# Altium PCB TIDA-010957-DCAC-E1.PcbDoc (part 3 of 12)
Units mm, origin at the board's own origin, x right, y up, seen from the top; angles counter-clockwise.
Board outline 300 x 300 mm, 4 copper layers (Top Layer, Layer 1, Layer 2, Bottom Layer), stack 1.787 mm thick; 1159 components, 619 nets, 3431 pads, 2942 vias.
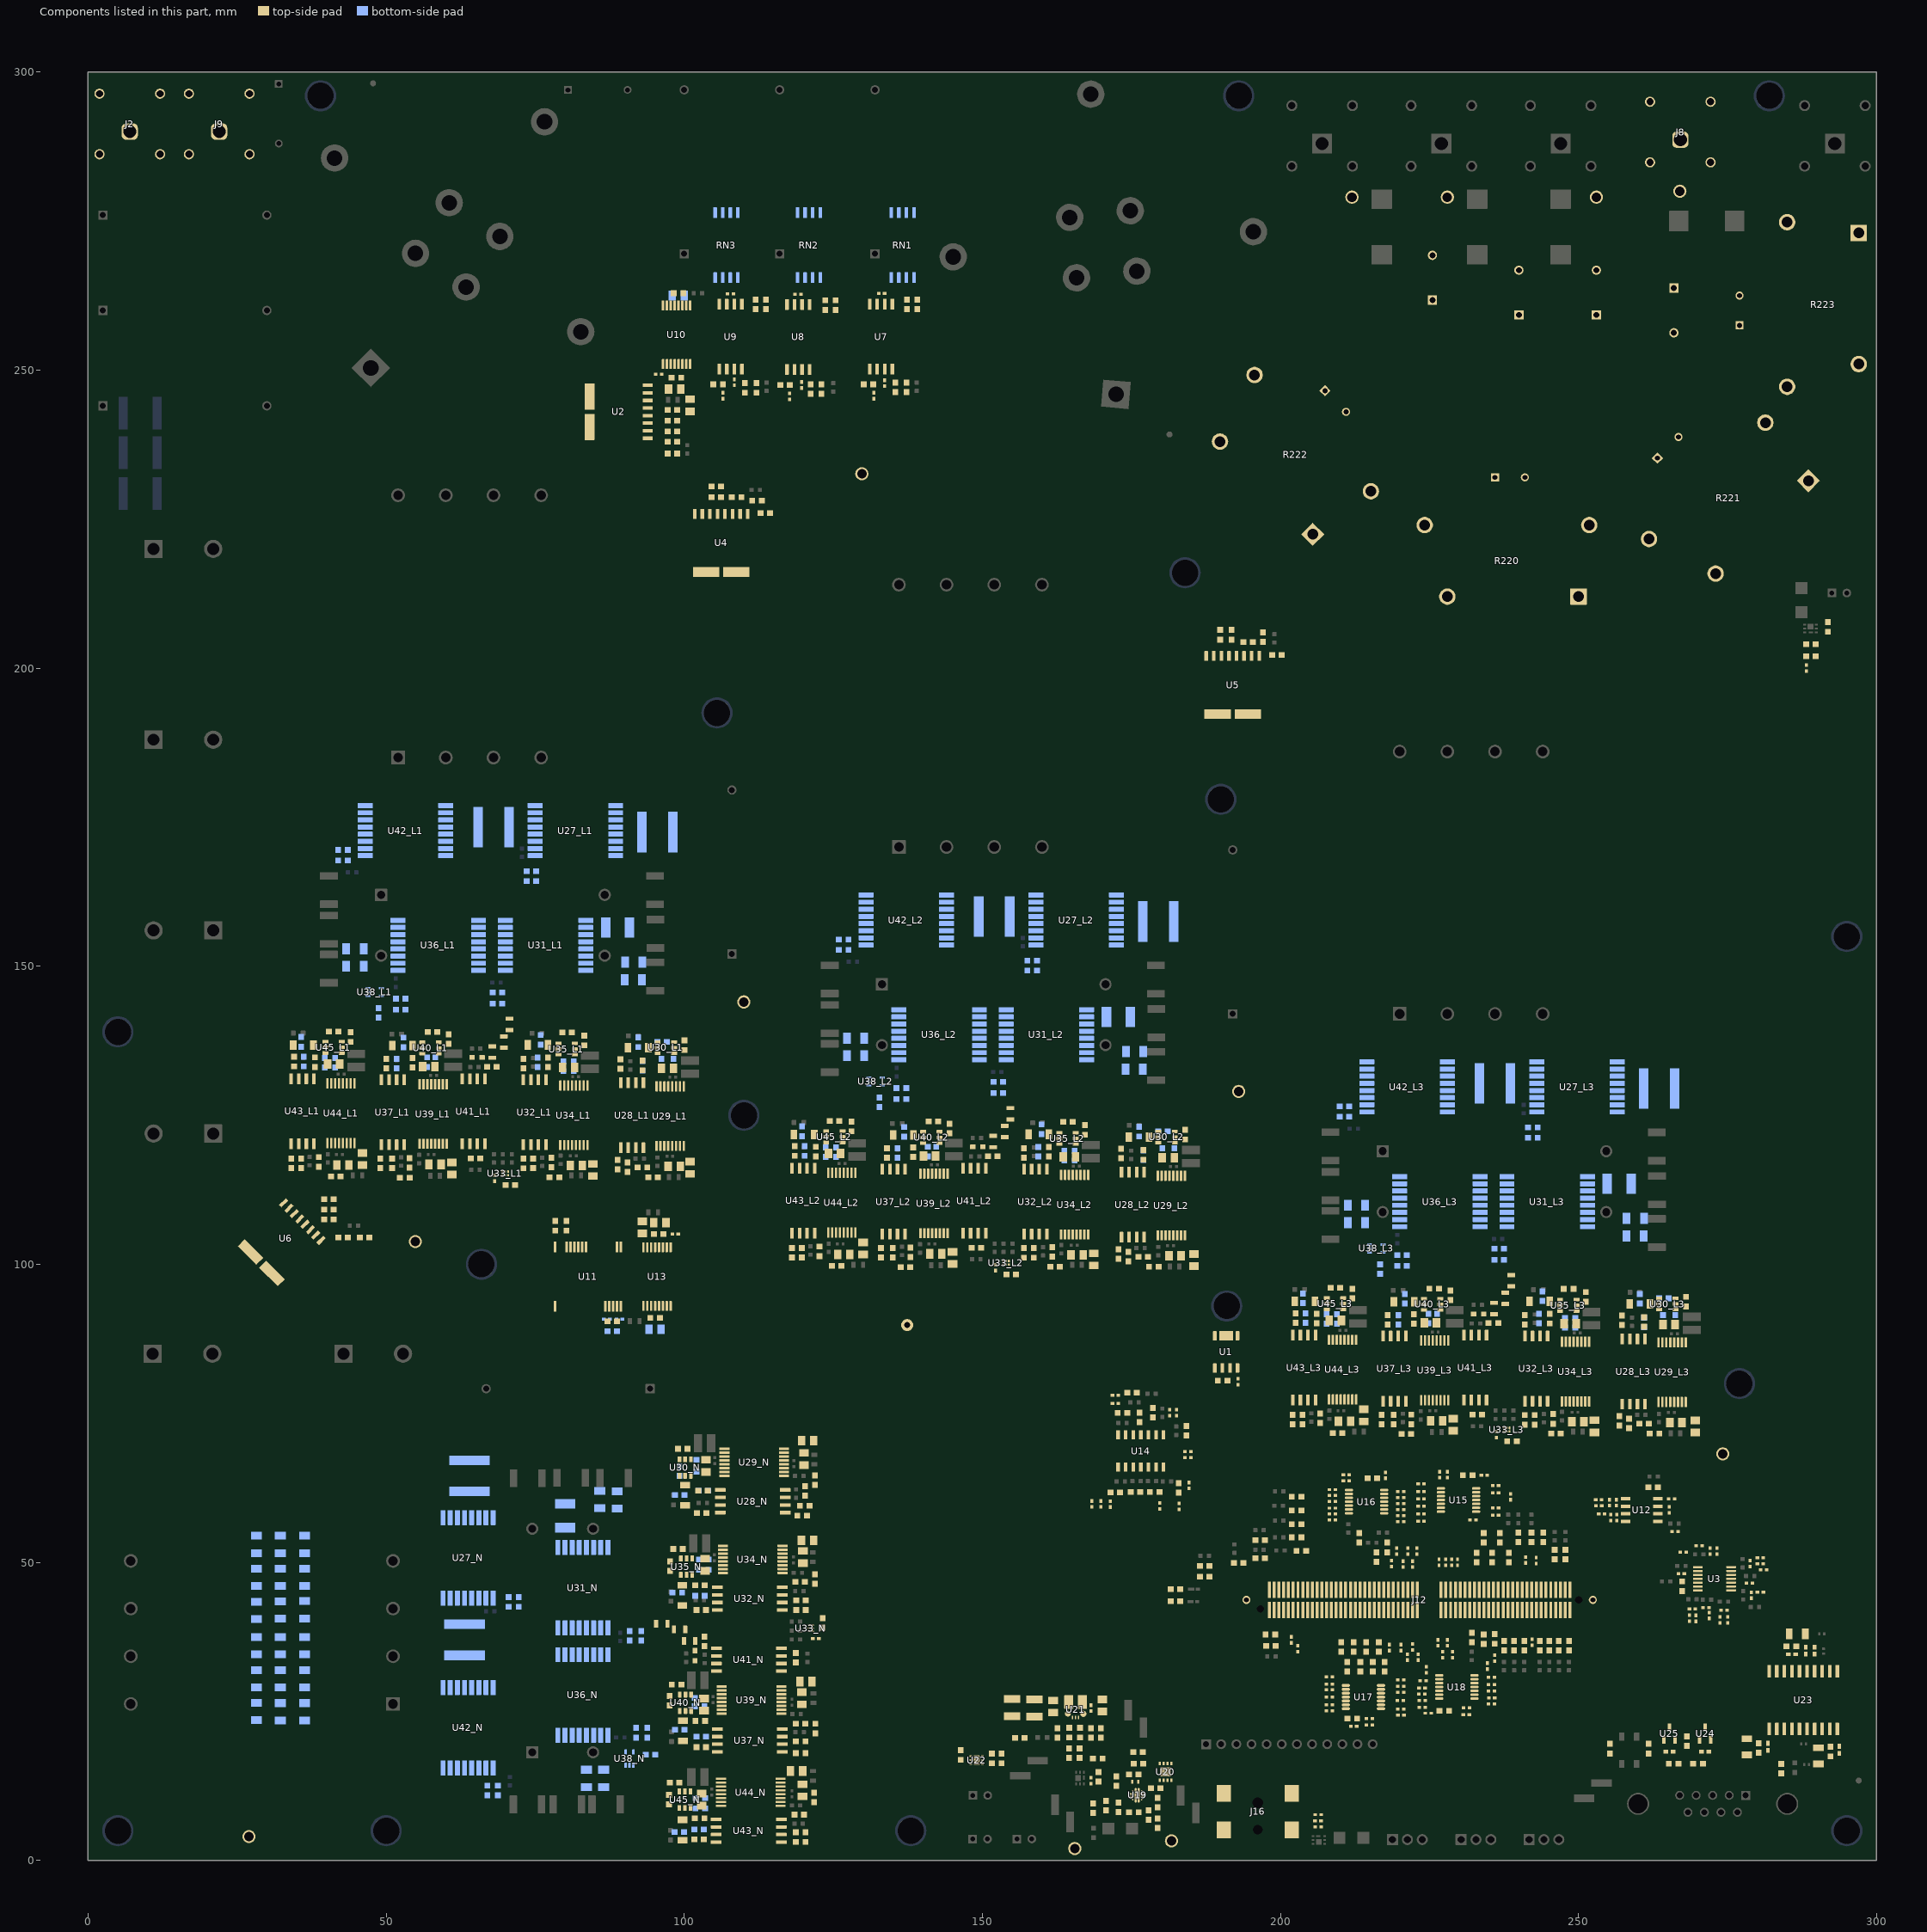
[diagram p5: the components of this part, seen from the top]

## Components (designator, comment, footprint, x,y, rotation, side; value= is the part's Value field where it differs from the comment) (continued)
R44 "ERJ-2RKF33R0X" 0402L 228.9,34.5 r90 top value=33.0
R45 "ERJ-2RKF33R0X" 0402L 228.7,50 r270 top value=33.0
R46 "ERJ-2RKF33R0X" 0402L 228,36.5 r90 top value=33.0
R47 "ERJ-2RKF33R0X" 0402L 227.7,50 r270 top value=33.0
R48 "ERJ-2RKF33R0X" 0402L 227.2,34.5 r90 top value=33.0
R49 "ERJ-2RKF33R0X" 0402L 226.6,50 r270 top value=33.0
R50 "ERJ-2RKF33R0X" 0402L 226.4,36.5 r90 top value=33.0
R51 "ERJ-2RKF33R0X" 0402L 222.9,51.9 r270 top value=33.0
R52 "ERJ-2RKF33R0X" 0402L 223.1,34.1 r90 top value=33.0
R53 "ERJ-2RKF33R0X" 0402L 222.2,49.7 r270 top value=33.0
R54 "ERJ-2RKF33R0X" 0402L 222.2,35.8 r90 top value=33.0
R55 "ERJ-2RKF33R0X" 0402L 221.4,51.9 r270 top value=33.0
R56 "ERJ-2RKF33R0X" 0402L 221.3,34.1 r90 top value=33.0
R57 "ERJ-2RKF33R0X" 0402L 220.6,49.7 r270 top value=33.0
R58 "ERJ-2RKF33R0X" 0402L 220.2,35.7 r90 top value=33.0
R59 "ERJ-2RKF33R0X" 0402L 219.5,51.9 r270 top value=33.0
R60 "ERJ-2RKF33R0X" 0402L 218.6,49.8 r270 top value=33.0
R61 "ERJ-2RKF33R0X" 0402L 218.3,35.7 r90 top value=33.0
R62 "RCS06030000Z0EA" 0603 217.9,52.5 r90 top value=0
R63 "RCS06030000Z0EA" 0603 217.5,32.5 r90 top value=0
R64 "RCS06030000Z0EA" 0603 216.1,50.9 r90 top value=0
R65 "RCS06030000Z0EA" 0603 216.5,35.8 r90 top value=0
R66 "RCS06030000Z0EA" 0603 213.2,54.1 r90 top value=0
R67 "RCS06030000Z0EA" 0603 215.5,32.5 r90 top value=0
R68 "RCS06030000Z0EA" 0603 202.7,61 r180 top value=0
R69 "RCS06030000Z0EA" 0603 214.4,35.8 r90 top value=0
R70 "RCS06030000Z0EA" 0603 202.7,58.7 r180 top value=0
R71 "RCS06030000Z0EA" 0603 213.4,32.5 r90 top value=0
R72 "RCS06030000Z0EA" 0603 202.7,56.4 r180 top value=0
R73 "RCS06030000Z0EA" 0603 202.7,54.2 r180 top value=0
R74 "RCS06030000Z0EA" 0603 196.589,53.741 r180 top value=0
R75 "RCS06030000Z0EA" 0603 203.5,51.9 r180 top value=0
R76 "RCS06030000Z0EA" 0603 196.6,50.7 r180 top value=0
R77 "RCS06030000Z0EA" 0603 193,49.9 r180 top value=0
R78 "RCS06030000Z0EA" 0603 187.3,49.4 r180 top value=0
R79 "ERJ-2RKF33R0X" 0402L 202.9,35.5 r90 top value=33.0
R80 "ERJ-2RKF33R0X" 0402L 201.8,37 r90 top value=33.0
R81 "RC0603JR-07680RL" 0603 182.4,45.5 r0 top value=680
R82 "RC0603JR-07680RL" 0603 182.4,43.5 r0 top value=680
R83 "PTCEL13R600LBE" FP-PTCEL13R600LBE_RADIAL-MFG 238.5,232 r0 top value=60Ω
R84 "RCS06030000Z0EA" 0603 212.3,35.8 r90 top value=0
R85 "PTCEL13R600LBE" FP-PTCEL13R600LBE_RADIAL-MFG 265,237 r45 top value=60Ω
R86 "RCS06030000Z0EA" 0603 211.2,32.5 r90 top value=0
R87 "PTCEL13R600LBE" FP-PTCEL13R600LBE_RADIAL-MFG 209.232,244.768 r315 top value=60Ω
R88 "RCS06030000Z0EA" 0603 210.2,35.8 r90 top value=0
R89 "IsoM5-275-B-L2" FP-IsoM5-275-B-L2_RADIAL-MFG 253,263 r90 top
R90 "IsoM5-275-B-L2" FP-IsoM5-275-B-L2_RADIAL-MFG 240,263 r90 top
R91 "IsoM5-275-B-L2" FP-IsoM5-275-B-L2_RADIAL-MFG 225.5,265.5 r90 top
R92 "PTCEL13R600LBE" FP-PTCEL13R600LBE_RADIAL-MFG 277,260 r90 top value=60Ω
R93 "CRCW0603499RFKEAC" 0603 284,15.4 r90 top value=499
R94 "IsoM5-275-B-L2" FP-IsoM5-275-B-L2_RADIAL-MFG 266,260 r270 top
R96 "ERJ-2RKF1000X" 0402L 288.2,200 r90 top value=100
R97 "CRCW060310K0FKEA" 0603 289,202 r180 top value=10.0k
R98 "MCS0402MD1002BE100" 0402L 271.4,42.4 r180 top value=10.0k
R99 "CRCW060310K0FKEA" 0603 98,236 r0 top value=10.0k
R100 "MCS0402MD1002BE100" 0402L 271.9,41.1 r270 top value=10.0k
R101 "CRCW0402309RFKED" 0402L 269.7,40.6 r270 top value=309
R102 "MCS0402MD1002BE100" 0402L 268.6,40.645 r270 top value=10.0k
R103 "MCS0402MD1002BE100" 0402L 269.1,42.2 r180 top value=10.0k
R104 "RC0603FR-0743K2L" 0603 98,239.7 r180 top value=43.2k
R105 "CRCW060310K0FKEA" 0603 98,241.5 r0 top value=10.0k
R106 "MCS0402MD1002BE100" 0402L 278.996,44.485 r270 top value=10.0k
R107 "MCS0402MD1002BE100" 0402L 280.5,45 r0 top value=10.0k
R108 "CRCW0402309RFKED" 0402L 275.05,40.363 r270 top value=309
R109 "CRCW060310K0FKEA" 0603 113.6,226 r0 top value=10.0k
R110 "MCS0402MD1002BE100" 0402L 273.75,40.363 r270 top value=10.0k
R111 "MCS0402MD1002BE100" 0402L 274.4,42 r180 top value=10.0k
R112 "RC0603FR-0743K2L" 0603 108.8,228.7 r0 top value=43.2k
R113 "CRCW060310K0FKEA" 0603 105.4,228.7 r0 top value=10.0k
R114 "MCS0402MD1002BE100" 0402L 278.685,46.5 r0 top value=10.0k
R115 "MCS0402MD1002BE100" 0402L 281.067,48.732 r0 top value=10.0k
R116 "CRCW0402309RFKED" 0402L 280.493,50.8 r0 top value=309
R117 "CRCW060310K0FKEA" 0603 199.4,202.2 r0 top value=10.0k
R118 "MCS0402MD1002BE100" 0402L 280.493,49.75 r0 top value=10.0k
R119 "MCS0402MD1002BE100" 0402L 278.8,49.8 r270 top value=10.0k
R120 "RC0603FR-0743K2L" 0603 194.6,204.4 r0 top value=43.2k
R121 "CRCW060310K0FKEA" 0603 189.9,205.6 r270 top value=10.0k
R122 "MCS0402MD1002BE100" 0402L 267.25,48.119 r180 top value=10.0k
R123 "CRCW060310K0FKEA" 0603 42.8,104.5 r0 top value=10.0k
R124 "MCS0402MD1002BE100" 0402L 273.2,51.9 r90 top value=10.0k
R125 "CRCW0402309RFKED" 0402L 267.55,51.684 r180 top value=309
R126 "MCS0402MD1002BE100" 0402L 272.1,51.9 r90 top value=10.0k
R127 "MCS0402MD1002BE100" 0402L 270.25,52.807 r0 top value=10.0k
R128 "RC0603FR-0743K2L" 0603 40.425,107.5 r0 top value=43.2k
R129 "CRCW060310K0FKEA" 0603 40.425,109.2 r180 top value=10.0k
R130 "ERJ-2RKF1000X" 0402L 133.6,247.8 r270 top value=100
R131 "ERJ-2RKF1000X" 0402L 131.8,245.7 r270 top value=100
R132 "ERJ-2RKF1000X" 0402L 119.705,247.494 r270 top value=100
R133 "ERJ-2RKF1000X" 0402L 117.7,245.6 r270 top value=100
R134 "ERJ-2RKF1000X" 0402L 108.405,247.945 r270 top value=100
R135 "ERJ-2RKF1000X" 0402L 106.5,245.7 r270 top value=100
R136 "CRCW040230K0FKED" 0402L 95.7,249.3 r0 top value=30.0k
R137 "ERA-2AEB153X" 0402L 256.4,57.5 r270 top value=15.0k
R138 "RC0402JR-070RL" 0402L 87.029,90.768 r180 bottom value=0
R139 "MCS0402MD1002BE100" 0402L 253.883,58.14 r180 top value=10.0k
R140 "CRCW0402309RFKED" 0402L 253.383,60.513 r180 top value=309
R141 "MCS0402MD1002BE100" 0402L 253.4,59.5 r180 top value=10.0k
R142 "ERA-2AEB153X" 0402L 256.35,60.013 r90 top value=15.0k
R143 "CRCW040230K0FKED" 0402L 98.5,105.1 r0 top value=30.0k
R144 "RT0603BRD0715K6L" 0603 178.6,75.1 r90 top value=15.6k
R145 "MCS0402MD1002BE100" 0402L 181.428,75.104 r90 top value=10.0k
R146 "ERJ-2RKF33R0X" 0402L 169.9,59.8 r270 top value=33.0
R147 "MCS0402MD1002BE100" 0402L 182.59,75.109 r90 top value=10.0k
R148 "RT0603BRD0715K6L" 0603 184.209,72.084 r90 top value=15.6k
R149 "RT0603BRD0715K6L" 0603 175.091,78.475 r0 top value=15.6k
R150 "MCS0402MD1002BE100" 0402L 172.32,78 r180 top value=10.0k
R151 "ERJ-2RKF33R0X" 0402L 168.4,59.8 r270 top value=33.0
R152 "MCS0402MD1002BE100" 0402L 172.32,76.663 r180 top value=10.0k
R153 "RT0603BRD0715K6L" 0603 173.495,75.051 r0 top value=15.6k
R154 "RT0603BRD0715K6L" 0603 175.673,61.784 r0 top value=15.6k
R155 "MCS0402MD1002BE100" 0402L 184.5,67.6 r0 top value=10.0k
R156 "ERJ-2RKF33R0X" 0402L 171.457,59.775 r270 top value=33.0
R157 "MCS0402MD1002BE100" 0402L 184.5,68.6 r0 top value=10.0k
R158 "RT0603BRD0715K6L" 0603 172.32,61.741 r0 top value=15.6k
R159 "RT0603BRD0715K6L" 0603 178.9,61.8 r180 top value=15.6k
R160 "MCS0402MD1002BE100" 0402L 179.765,59.475 r270 top value=10.0k
R161 "ERJ-2RKF33R0X" 0402L 184.7,62.9 r270 top value=33.0
R162 "MCS0402MD1002BE100" 0402L 183,59.4 r270 top value=10.0k
R163 "RT0603BRD0715K6L" 0603 182.94,62.509 r270 top value=15.6k
R164 "CRCW040210R0JNED" 0402L 234.2,64.6 r0 top value=10
R165 "ERJ-2RKF33R0X" 0402L 223.6,60.65 r180 top value=33.0
R166 "ERJ-2RKF33R0X" 0402L 223.6,56.9 r180 top value=33.0
R167 "ERJ-2RKF33R0X" 0402L 232.3,57.1 r180 top value=33.0
R168 "ERJ-2RKF33R0X" 0402L 238.6,61 r90 top value=33.0
R169 "CRCW040210K0FKED" 0402L 228,64.7 r270 top value=10.0k
R170 "CRCW040210K0FKED" 0402L 223.6,63.15 r0 top value=10.0k
R171 "CRCW040210K0FKED" 0402L 223.6,59.4 r0 top value=10.0k
R172 "CRCW040210K0FKED" 0402L 236.1,57.9 r180 top value=10.0k
R173 "CRCW040210K0FKED" 0402L 236.1,62.9 r180 top value=10.0k
R174 "CRCW040210R0JNED" 0402L 217.6,64.6 r90 top value=10
R175 "CRCW040210R0JNED" 0402L 212.3,22.5 r0 top value=10
R176 "ERJ-2RKF33R0X" 0402L 208.7,60.2 r180 top value=33.0
R177 "ERJ-2RKF33R0X" 0402L 220.1,26.8 r0 top value=33.0
R178 "ERJ-2RKF33R0X" 0402L 208.7,57.1 r180 top value=33.0
R179 "ERJ-2RKF33R0X" 0402L 220.2,30.3 r0 top value=33.0
R180 "ERJ-2RKF33R0X" 0402L 220.2,56.85 r0 top value=33.0
R181 "ERJ-2RKF33R0X" 0402L 208.2,30.8 r180 top value=33.0
R182 "ERJ-2RKF33R0X" 0402L 220.2,59.85 r0 top value=33.0
R183 "ERJ-2RKF33R0X" 0402L 208.2,27.4 r180 top value=33.0
R184 "CRCW040210K0FKED" 0402L 211.048,64.708 r0 top value=10.0k
R185 "CRCW040210K0FKED" 0402L 208.7,62.2 r0 top value=10.0k
R186 "CRCW040210K0FKED" 0402L 208.7,58.1 r0 top value=10.0k
R187 "CRCW040210K0FKED" 0402L 220.2,57.85 r180 top value=10.0k
R188 "CRCW040210K0FKED" 0402L 220.2,60.85 r180 top value=10.0k
R189 "CRCW040210K0FKED" 0402L 214.9,23.8 r0 top value=10.0k
R190 "CRCW040210K0FKED" 0402L 220.216,24.369 r180 top value=10.0k
R191 "CRCW040210K0FKED" 0402L 220.2,28.2 r180 top value=10.0k
R192 "CRCW040210K0FKED" 0402L 208.2,29.6 r0 top value=10.0k
R193 "CRCW040210K0FKED" 0402L 208.2,26.1 r0 top value=10.0k
R194 "CRCW040210R0JNED" 0402L 224.8,24.7 r180 top value=10
R195 "ERJ-2RKF33R0X" 0402L 235.4,28.4 r0 top value=33.0
R196 "ERJ-2RKF33R0X" 0402L 234.7,32.6 r90 top value=33.0
R197 "ERJ-2RKF33R0X" 0402L 224.5,32 r90 top value=33.0
R198 "ERJ-2RKF33R0X" 0402L 223.7,27.9 r180 top value=33.0
R199 "CRCW040210K0FKED" 0402L 231.183,24.472 r0 top value=10.0k
R200 "CRCW040210K0FKED" 0402L 235.45,27.25 r180 top value=10.0k
R201 "CRCW040210K0FKED" 0402L 235.4,29.5 r180 top value=10.0k
R202 "CRCW040210K0FKED" 0402L 223.95,30.15 r0 top value=10.0k
R203 "CRCW040210K0FKED" 0402L 223.794,26.83 r0 top value=10.0k
R204 "RC0603FR-07470KL" 0603 179.391,6.246 r270 top value=470k
R205 "RC0603FR-0747KL" 0603 176.139,18.175 r180 top value=47.0k
R206 "RC0603FR-071K1L" 0603 170.729,9.175 r90 top value=1.10k
R207 "RC0603FR-075K6L" 0603 176.179,16.25 r0 top value=5.60k
R208 "RC0603FR-0711KL" 0603 179.391,9.725 r270 top value=11.0k
R209 "RC0603FR-0747KL" 0603 179.079,12.125 r0 top value=47.0k
R210 "RC0603FR-072KL" 0603 168.612,8.761 r270 top value=2.00k
R211 "RC0603FR-0747KL" 0603 177.9,7.6 r90 top value=47.0k
R212 "RC0603FR-0715KL" 0603 169.482,14.05 r270 top value=15.0k
R213 "RC0603FR-0754K9L" 0603 169.371,17.096 r0 top value=54.9k
R214 "RC0603FR-07220KL" 0603 169.858,21.396 r270 top value=220k
R215 "RC0603FR-0730KL" 0603 166.383,21.425 r90 top value=30.0k
R216 "RG1608P-103-B-T5" 0603 164.538,17.971 r90 top value=10.0k
R217 "CRCW0603499RFKEAC" 0603 156.283,20.55 r0 top value=499
R218 "RC0603FR-0730KL" 0603 162.608,21.396 r270 top value=30.0k
R219 "RC0603FR-0747KL" 0603 164.583,21.425 r90 top value=47.0k
R220 "FTR-K3AB012W-WG" FP-FTR-K3AB012W-WG_PTH_RELAY_30MM1_15MM7-MFG 238,217.75 r180 top
R221 "FTR-K3AB012W-WG" FP-FTR-K3AB012W-WG_PTH_RELAY_30MM1_15MM7-MFG 276,227 r225 top
R222 "FTR-K3AB012W-WG" FP-FTR-K3AB012W-WG_PTH_RELAY_30MM1_15MM7-MFG 201,235 r135 top
R223 "FTR-K3AB012W-WG" FP-FTR-K3AB012W-WG_PTH_RELAY_30MM1_15MM7-MFG 291.25,261 r270 top
R224 "CRCW040210K0FKED" 0402 288.1,35.2 r90 top value=10.0k
R225 "RCS06030000Z0EA" 0603 261.75,18.75 r90 top value=0
R226 "RT0603DRE0759R7L" 0603 265.95,16.25 r180 top value=59.7
R227 "RT0603DRE0759R7L" 0603 270.05,16.25 r180 top value=59.7
R228 "RCS06030000Z0EA" 0603 255.25,18.75 r90 top value=0
R278_L1 "CRCW060333R0JNEA" 0603 90.48,116.292 r90 top value=33 (schematic designator R278)
R278_L2 "CRCW060333R0JNEA" 0603 174.48,101.292 r90 top value=33 (schematic designator R278)
R278_L3 "CRCW060333R0JNEA" 0603 258.48,73.292 r90 top value=33 (schematic designator R278)
R278_N "CRCW060333R0JNEA" 0603 120.208,59.48 r180 top value=33 (schematic designator R278)
R279_L1 "CRCW060333R0JNEA" 0603 93,133.273 r90 bottom value=33 (schematic designator R279)
R279_L2 "CRCW060333R0JNEA" 0603 177,118.273 r90 bottom value=33 (schematic designator R279)
R279_L3 "CRCW060333R0JNEA" 0603 261,90.273 r90 bottom value=33 (schematic designator R279)
R279_N "CRCW060333R0JNEA" 0603 103.227,62 r180 bottom value=33 (schematic designator R279)
R281_L1 "CRCW1206100RFKEAHP" 1206 91.467,147.75 r0 bottom value=100 (schematic designator R281)
R281_L2 "CRCW1206100RFKEAHP" 1206 175.467,132.75 r0 bottom value=100 (schematic designator R281)
R281_L3 "CRCW1206100RFKEAHP" 1206 259.467,104.75 r0 bottom value=100 (schematic designator R281)
R281_N "CRCW1206100RFKEAHP" 1206 88.75,60.467 r90 bottom value=100 (schematic designator R281)
R282_L1 "CRCW1206100RFKEAHP" 1206 91.52,150.686 r0 bottom value=100 (schematic designator R282)
R282_L2 "CRCW1206100RFKEAHP" 1206 175.52,135.686 r0 bottom value=100 (schematic designator R282)
R282_L3 "CRCW1206100RFKEAHP" 1206 259.52,107.686 r0 bottom value=100 (schematic designator R282)
R282_N "CRCW1206100RFKEAHP" 1206 85.814,60.52 r90 bottom value=100 (schematic designator R282)
R283_L1 "CRCW060356K0JNEA" 0603 74.351,164.25 r0 bottom value=56k (schematic designator R283)
R283_L2 "CRCW060356K0JNEA" 0603 158.351,149.25 r0 bottom value=56k (schematic designator R283)
R283_L3 "CRCW060356K0JNEA" 0603 242.351,121.25 r0 bottom value=56k (schematic designator R283)
R283_N "CRCW060356K0JNEA" 0603 72.25,43.351 r90 bottom value=56k (schematic designator R283)
R284_L1 "CRCW060310K0FKEA" 0603 93,116.255 r180 top value=10.0k (schematic designator R284)
R284_L2 "CRCW060310K0FKEA" 0603 177,101.255 r180 top value=10.0k (schematic designator R284)
R284_L3 "CRCW060310K0FKEA" 0603 261,73.255 r180 top value=10.0k (schematic designator R284)
R284_N "CRCW060310K0FKEA" 0603 120.245,62 r270 top value=10.0k (schematic designator R284)
R285_L1 "RC0603FR-0710KL" 0603 92.275,137.24 r270 bottom value=10.0k (schematic designator R285)
R285_L2 "RC0603FR-0710KL" 0603 176.275,122.24 r270 bottom value=10.0k (schematic designator R285)
R285_L3 "RC0603FR-0710KL" 0603 260.275,94.24 r270 bottom value=10.0k (schematic designator R285)
R285_N "RC0603FR-0710KL" 0603 99.26,61.275 r0 bottom value=10.0k (schematic designator R285)
R286_L1 "RC0603FR-07270KL" 0603 98.204,133.669 r270 bottom value=270k (schematic designator R286)
R286_L2 "RC0603FR-07270KL" 0603 182.204,118.669 r270 bottom value=270k (schematic designator R286)
R286_L3 "RC0603FR-07270KL" 0603 266.204,90.669 r270 bottom value=270k (schematic designator R286)
R286_N "RC0603FR-07270KL" 0603 102.831,67.204 r0 bottom value=270k (schematic designator R286)
R287_L1 "CRCW060310K0FKEA" 0603 94.763,114.583 r180 top value=10.0k (schematic designator R287)
R287_L2 "CRCW060310K0FKEA" 0603 178.763,99.583 r180 top value=10.0k (schematic designator R287)
R287_L3 "CRCW060310K0FKEA" 0603 262.763,71.583 r180 top value=10.0k (schematic designator R287)
R287_N "CRCW060310K0FKEA" 0603 121.917,63.763 r270 top value=10.0k (schematic designator R287)
R288_L1 "RC0603FR-07100KL" 0603 96.172,133.669 r90 bottom value=100k (schematic designator R288)
R288_L2 "RC0603FR-07100KL" 0603 180.172,118.669 r90 bottom value=100k (schematic designator R288)
R288_L3 "RC0603FR-07100KL" 0603 264.172,90.669 r90 bottom value=100k (schematic designator R288)
R288_N "RC0603FR-07100KL" 0603 102.831,65.172 r180 bottom value=100k (schematic designator R288)
R289_L1 "RC0603FR-07825KL" 0603 96.313,137.295 r180 bottom value=825k (schematic designator R289)
R289_L2 "RC0603FR-07825KL" 0603 180.313,122.295 r180 bottom value=825k (schematic designator R289)
R289_L3 "RC0603FR-07825KL" 0603 264.313,94.295 r180 bottom value=825k (schematic designator R289)
R289_N "RC0603FR-07825KL" 0603 99.205,65.313 r270 bottom value=825k (schematic designator R289)
R290_L1 "RC0603FR-0771K5L" 0603 100.047,136.74 r90 top value=71.5k (schematic designator R290)
R290_L2 "RC0603FR-0771K5L" 0603 184.047,121.74 r90 top value=71.5k (schematic designator R290)
R290_L3 "RC0603FR-0771K5L" 0603 268.047,93.74 r90 top value=71.5k (schematic designator R290)
R290_N "RC0603FR-0771K5L" 0603 99.76,69.047 r180 top value=71.5k (schematic designator R290)
R291_L1 "CRCW060333R0JNEA" 0603 74.66,116.911 r90 top value=33 (schematic designator R291)
R291_L2 "CRCW060333R0JNEA" 0603 158.66,101.911 r90 top value=33 (schematic designator R291)
R291_L3 "CRCW060333R0JNEA" 0603 242.66,73.911 r90 top value=33 (schematic designator R291)
R291_N "CRCW060333R0JNEA" 0603 119.589,43.66 r180 top value=33 (schematic designator R291)
R292_L1 "CRCW060333R0JNEA" 0603 75.385,133.882 r90 bottom value=33 (schematic designator R292)
R292_L2 "CRCW060333R0JNEA" 0603 159.385,118.882 r90 bottom value=33 (schematic designator R292)
R292_L3 "CRCW060333R0JNEA" 0603 243.385,90.882 r90 bottom value=33 (schematic designator R292)
R292_N "CRCW060333R0JNEA" 0603 102.618,44.385 r180 bottom value=33 (schematic designator R292)
R293_L1 "ERJ-2RKF33R0X" 0402L 68.2,114.434 r90 top value=33.0 (schematic designator R293)
R293_L2 "ERJ-2RKF33R0X" 0402L 152.2,99.434 r90 top value=33.0 (schematic designator R293)
R293_L3 "ERJ-2RKF33R0X" 0402L 236.2,71.434 r90 top value=33.0 (schematic designator R293)
R293_N "ERJ-2RKF33R0X" 0402L 122.066,37.2 r180 top value=33.0 (schematic designator R293)
R294_L1 "CRCW060356K0JNEA" 0603 68.69,143.725 r0 bottom value=56k (schematic designator R294)
R294_L2 "CRCW060356K0JNEA" 0603 152.69,128.725 r0 bottom value=56k (schematic designator R294)
R294_L3 "CRCW060356K0JNEA" 0603 236.69,100.725 r0 bottom value=56k (schematic designator R294)
R294_N "CRCW060356K0JNEA" 0603 92.775,37.69 r90 bottom value=56k (schematic designator R294)
R295_L1 "CRCW060310K0FKEA" 0603 77.75,117.063 r90 top value=10.0k (schematic designator R295)
R295_L2 "CRCW060310K0FKEA" 0603 161.75,102.063 r90 top value=10.0k (schematic designator R295)
R295_L3 "CRCW060310K0FKEA" 0603 245.75,74.063 r90 top value=10.0k (schematic designator R295)
R295_N "CRCW060310K0FKEA" 0603 119.437,46.75 r180 top value=10.0k (schematic designator R295)
R296_L1 "RC0603FR-0710KL" 0603 75.93,137.657 r270 bottom value=10.0k (schematic designator R296)
R296_L2 "RC0603FR-0710KL" 0603 159.93,122.657 r270 bottom value=10.0k (schematic designator R296)
R296_L3 "RC0603FR-0710KL" 0603 243.93,94.657 r270 bottom value=10.0k (schematic designator R296)
R296_N "RC0603FR-0710KL" 0603 98.843,44.93 r0 bottom value=10.0k (schematic designator R296)
R297_L1 "RC0603FR-07270KL" 0603 81.456,133.207 r270 bottom value=270k (schematic designator R297)
R297_L2 "RC0603FR-07270KL" 0603 165.456,118.207 r270 bottom value=270k (schematic designator R297)
R297_L3 "RC0603FR-07270KL" 0603 249.456,90.207 r270 bottom value=270k (schematic designator R297)
R297_N "RC0603FR-07270KL" 0603 103.293,50.456 r0 bottom value=270k (schematic designator R297)
R298_L1 "CRCW060310K0FKEA" 0603 78.225,114.583 r180 top value=10.0k (schematic designator R298)
R298_L2 "CRCW060310K0FKEA" 0603 162.225,99.583 r180 top value=10.0k (schematic designator R298)
R298_L3 "CRCW060310K0FKEA" 0603 246.225,71.583 r180 top value=10.0k (schematic designator R298)
R298_N "CRCW060310K0FKEA" 0603 121.917,47.225 r270 top value=10.0k (schematic designator R298)
R299_L1 "RC0603FR-07100KL" 0603 79.736,133.207 r90 bottom value=100k (schematic designator R299)
R299_L2 "RC0603FR-07100KL" 0603 163.736,118.207 r90 bottom value=100k (schematic designator R299)
R299_L3 "RC0603FR-07100KL" 0603 247.736,90.207 r90 bottom value=100k (schematic designator R299)
R299_N "RC0603FR-07100KL" 0603 103.293,48.736 r180 bottom value=100k (schematic designator R299)
R300_L1 "RC0603FR-07825KL" 0603 80.344,138.875 r180 top value=825k (schematic designator R300)
R300_L2 "RC0603FR-07825KL" 0603 164.344,123.875 r180 top value=825k (schematic designator R300)
R300_L3 "RC0603FR-07825KL" 0603 248.344,95.875 r180 top value=825k (schematic designator R300)
R300_N "RC0603FR-07825KL" 0603 97.625,49.344 r270 top value=825k (schematic designator R300)
R301_L1 "RC0603FR-0771K5L" 0603 83.244,137.534 r90 top value=71.5k (schematic designator R301)
R301_L2 "RC0603FR-0771K5L" 0603 167.244,122.534 r90 top value=71.5k (schematic designator R301)
R301_L3 "RC0603FR-0771K5L" 0603 251.244,94.534 r90 top value=71.5k (schematic designator R301)
R301_N "RC0603FR-0771K5L" 0603 98.966,52.244 r180 top value=71.5k (schematic designator R301)
R302_L1 "CRCW060333R0JNEA" 0603 51,116.955 r90 top value=33 (schematic designator R302)
R302_L2 "CRCW060333R0JNEA" 0603 135,101.955 r90 top value=33 (schematic designator R302)
R302_L3 "CRCW060333R0JNEA" 0603 219,73.955 r90 top value=33 (schematic designator R302)
R302_N "CRCW060333R0JNEA" 0603 119.545,20 r180 top value=33 (schematic designator R302)
R303_L1 "CRCW060333R0JNEA" 0603 51.764,133.666 r90 bottom value=33 (schematic designator R303)
R303_L2 "CRCW060333R0JNEA" 0603 135.764,118.666 r90 bottom value=33 (schematic designator R303)
R303_L3 "CRCW060333R0JNEA" 0603 219.764,90.666 r90 bottom value=33 (schematic designator R303)
R303_N "CRCW060333R0JNEA" 0603 102.834,20.764 r180 bottom value=33 (schematic designator R303)
R304_L1 "CRCW060356K0JNEA" 0603 52.422,142.725 r0 bottom value=56k (schematic designator R304)
R304_L2 "CRCW060356K0JNEA" 0603 136.422,127.725 r0 bottom value=56k (schematic designator R304)
R304_L3 "CRCW060356K0JNEA" 0603 220.422,99.725 r0 bottom value=56k (schematic designator R304)
R304_N "CRCW060356K0JNEA" 0603 93.775,21.422 r90 bottom value=56k (schematic designator R304)
R305_L1 "CRCW060310K0FKEA" 0603 53.929,116.984 r90 top value=10.0k (schematic designator R305)
R305_L2 "CRCW060310K0FKEA" 0603 137.929,101.984 r90 top value=10.0k (schematic designator R305)
R305_L3 "CRCW060310K0FKEA" 0603 221.929,73.984 r90 top value=10.0k (schematic designator R305)
R305_N "CRCW060310K0FKEA" 0603 119.516,22.929 r180 top value=10.0k (schematic designator R305)
R306_L1 "RC0603FR-0710KL" 0603 52.897,137.233 r270 bottom value=10.0k (schematic designator R306)
R306_L2 "RC0603FR-0710KL" 0603 136.897,122.233 r270 bottom value=10.0k (schematic designator R306)
R306_L3 "RC0603FR-0710KL" 0603 220.897,94.233 r270 bottom value=10.0k (schematic designator R306)
R306_N "RC0603FR-0710KL" 0603 99.267,21.897 r0 bottom value=10.0k (schematic designator R306)
R307_L1 "RC0603FR-07270KL" 0603 58.258,133.907 r270 bottom value=270k (schematic designator R307)
R307_L2 "RC0603FR-07270KL" 0603 142.258,118.907 r270 bottom value=270k (schematic designator R307)
R307_L3 "RC0603FR-07270KL" 0603 226.258,90.907 r270 bottom value=270k (schematic designator R307)
R307_N "RC0603FR-07270KL" 0603 102.593,27.258 r0 bottom value=270k (schematic designator R307)
R308_L1 "CRCW060310K0FKEA" 0603 53.13,114.517 r180 top value=10.0k (schematic designator R308)
R308_L2 "CRCW060310K0FKEA" 0603 137.13,99.517 r180 top value=10.0k (schematic designator R308)
R308_L3 "CRCW060310K0FKEA" 0603 221.13,71.517 r180 top value=10.0k (schematic designator R308)
R308_N "CRCW060310K0FKEA" 0603 121.983,22.13 r270 top value=10.0k (schematic designator R308)
R309_L1 "RC0603FR-07100KL" 0603 56.86,133.907 r90 bottom value=100k (schematic designator R309)
R309_L2 "RC0603FR-07100KL" 0603 140.86,118.907 r90 bottom value=100k (schematic designator R309)
R309_L3 "RC0603FR-07100KL" 0603 224.86,90.907 r90 bottom value=100k (schematic designator R309)
R309_N "RC0603FR-07100KL" 0603 102.593,25.86 r180 bottom value=100k (schematic designator R309)
R310_L1 "RC0603FR-07825KL" 0603 57.783,138.942 r180 top value=825k (schematic designator R310)
R310_L2 "RC0603FR-07825KL" 0603 141.783,123.942 r180 top value=825k (schematic designator R310)
R310_L3 "RC0603FR-07825KL" 0603 225.783,95.942 r180 top value=825k (schematic designator R310)
R310_N "RC0603FR-07825KL" 0603 97.558,26.783 r270 top value=825k (schematic designator R310)
R311_L1 "RC0603FR-0771K5L" 0603 60.5,137.784 r90 top value=71.5k (schematic designator R311)
R311_L2 "RC0603FR-0771K5L" 0603 144.5,122.784 r90 top value=71.5k (schematic designator R311)
R311_L3 "RC0603FR-0771K5L" 0603 228.5,94.784 r90 top value=71.5k (schematic designator R311)
R311_N "RC0603FR-0771K5L" 0603 98.716,29.5 r180 top value=71.5k (schematic designator R311)
R312_L1 "TNPV0805680KBEEA" FP-TNPV0805680KBEEA_0805-MFG 67.829,135.59 r90 top value=680k (schematic designator R312)
R312_L2 "TNPV0805680KBEEA" FP-TNPV0805680KBEEA_0805-MFG 151.829,120.59 r90 top value=680k (schematic designator R312)
R312_L3 "TNPV0805680KBEEA" FP-TNPV0805680KBEEA_0805-MFG 235.829,92.59 r90 top value=680k (schematic designator R312)
R312_N "TNPV0805680KBEEA" FP-TNPV0805680KBEEA_0805-MFG 100.91,36.829 r180 top value=680k (schematic designator R312)
R313_L1 "TNPV0805680KBEEA" FP-TNPV0805680KBEEA_0805-MFG 69.739,137.282 r90 top value=680k (schematic designator R313)
R313_L2 "TNPV0805680KBEEA" FP-TNPV0805680KBEEA_0805-MFG 153.739,122.282 r90 top value=680k (schematic designator R313)
R313_L3 "TNPV0805680KBEEA" FP-TNPV0805680KBEEA_0805-MFG 237.739,94.282 r90 top value=680k (schematic designator R313)
R313_N "TNPV0805680KBEEA" FP-TNPV0805680KBEEA_0805-MFG 99.218,38.739 r180 top value=680k (schematic designator R313)
R314_L1 "TNPV0805680KBEEA" FP-TNPV0805680KBEEA_0805-MFG 70.7,140.25 r90 top value=680k (schematic designator R314)
R314_L2 "TNPV0805680KBEEA" FP-TNPV0805680KBEEA_0805-MFG 154.7,125.25 r90 top value=680k (schematic designator R314)
R314_L3 "TNPV0805680KBEEA" FP-TNPV0805680KBEEA_0805-MFG 238.7,97.25 r90 top value=680k (schematic designator R314)
R314_N "TNPV0805680KBEEA" FP-TNPV0805680KBEEA_0805-MFG 96.25,39.7 r180 top value=680k (schematic designator R314)
R315_L1 "RT0603BRE078KL" FP-RT0603BRE078KL_0603-MFG 65.257,134.682 r0 top value=8k (schematic designator R315)
R315_L2 "RT0603BRE078KL" FP-RT0603BRE078KL_0603-MFG 149.257,119.682 r0 top value=8k (schematic designator R315)
R315_L3 "RT0603BRE078KL" FP-RT0603BRE078KL_0603-MFG 233.257,91.682 r0 top value=8k (schematic designator R315)
R315_N "RT0603BRE078KL" FP-RT0603BRE078KL_0603-MFG 101.818,34.357 r90 top value=8k (schematic designator R315)
R316_L1 "CRCW060333R0JNEA" 0603 35.725,116.955 r90 top value=33 (schematic designator R316)
R316_L2 "CRCW060333R0JNEA" 0603 119.725,101.955 r90 top value=33 (schematic designator R316)
R316_L3 "CRCW060333R0JNEA" 0603 203.725,73.955 r90 top value=33 (schematic designator R316)
R316_N "CRCW060333R0JNEA" 0603 119.545,4.725 r180 top value=33 (schematic designator R316)
R317_L1 "CRCW060333R0JNEA" 0603 36.2,133.998 r90 bottom value=33 (schematic designator R317)
R317_L2 "CRCW060333R0JNEA" 0603 120.2,118.998 r90 bottom value=33 (schematic designator R317)
R317_L3 "CRCW060333R0JNEA" 0603 204.2,90.998 r90 bottom value=33 (schematic designator R317)
R317_N "CRCW060333R0JNEA" 0603 102.502,5.2 r180 bottom value=33 (schematic designator R317)
R319_L1 "CRCW1206100RFKEAHP" 1206 44.769,150 r0 bottom value=100 (schematic designator R319)
R319_L2 "CRCW1206100RFKEAHP" 1206 128.769,135 r0 bottom value=100 (schematic designator R319)
R319_L3 "CRCW1206100RFKEAHP" 1206 212.769,107 r0 bottom value=100 (schematic designator R319)
R319_N "CRCW1206100RFKEAHP" 1206 86.5,13.769 r90 bottom value=100 (schematic designator R319)
R320_L1 "CRCW1206100RFKEAHP" 1206 44.769,152.9 r0 bottom value=100 (schematic designator R320)
R320_L2 "CRCW1206100RFKEAHP" 1206 128.769,137.9 r0 bottom value=100 (schematic designator R320)
R320_L3 "CRCW1206100RFKEAHP" 1206 212.769,109.9 r0 bottom value=100 (schematic designator R320)
R320_N "CRCW1206100RFKEAHP" 1206 83.6,13.769 r90 bottom value=100 (schematic designator R320)
R321_L1 "CRCW060356K0JNEA" 0603 42.75,167.75 r180 bottom value=56k (schematic designator R321)
R321_L2 "CRCW060356K0JNEA" 0603 126.75,152.75 r180 bottom value=56k (schematic designator R321)
R321_L3 "CRCW060356K0JNEA" 0603 210.75,124.75 r180 bottom value=56k (schematic designator R321)
R321_N "CRCW060356K0JNEA" 0603 68.75,11.75 r270 bottom value=56k (schematic designator R321)
R322_L1 "CRCW060310K0FKEA" 0603 38.685,117.18 r90 top value=10.0k (schematic designator R322)
R322_L2 "CRCW060310K0FKEA" 0603 122.685,102.18 r90 top value=10.0k (schematic designator R322)
R322_L3 "CRCW060310K0FKEA" 0603 206.685,74.18 r90 top value=10.0k (schematic designator R322)
R322_N "CRCW060310K0FKEA" 0603 119.32,7.685 r180 top value=10.0k (schematic designator R322)
R323_L1 "RC0603FR-0710KL" 0603 35.768,137.309 r270 bottom value=10.0k (schematic designator R323)
R323_L2 "RC0603FR-0710KL" 0603 119.768,122.309 r270 bottom value=10.0k (schematic designator R323)
R323_L3 "RC0603FR-0710KL" 0603 203.768,94.309 r270 bottom value=10.0k (schematic designator R323)
R323_N "RC0603FR-0710KL" 0603 99.191,4.768 r0 bottom value=10.0k (schematic designator R323)
R324_L1 "RC0603FR-07270KL" 0603 41.476,133.823 r270 bottom value=270k (schematic designator R324)
R324_L2 "RC0603FR-07270KL" 0603 125.476,118.823 r270 bottom value=270k (schematic designator R324)
R324_L3 "RC0603FR-07270KL" 0603 209.476,90.823 r270 bottom value=270k (schematic designator R324)
R324_N "RC0603FR-07270KL" 0603 102.677,10.476 r0 bottom value=270k (schematic designator R324)
R325_L1 "CRCW060310K0FKEA" 0603 41.569,114.709 r0 top value=10.0k (schematic designator R325)
R325_L2 "CRCW060310K0FKEA" 0603 125.569,99.709 r0 top value=10.0k (schematic designator R325)
R325_L3 "CRCW060310K0FKEA" 0603 209.569,71.709 r0 top value=10.0k (schematic designator R325)
R325_N "CRCW060310K0FKEA" 0603 121.791,10.569 r90 top value=10.0k (schematic designator R325)
R326_L1 "RC0603FR-07100KL" 0603 39.726,133.823 r90 bottom value=100k (schematic designator R326)
R326_L2 "RC0603FR-07100KL" 0603 123.726,118.823 r90 bottom value=100k (schematic designator R326)
R326_L3 "RC0603FR-07100KL" 0603 207.726,90.823 r90 bottom value=100k (schematic designator R326)
R326_N "RC0603FR-07100KL" 0603 102.677,8.726 r180 bottom value=100k (schematic designator R326)
R327_L1 "RC0603FR-07825KL" 0603 41.203,139.059 r180 top value=825k (schematic designator R327)
R327_L2 "RC0603FR-07825KL" 0603 125.203,124.059 r180 top value=825k (schematic designator R327)
R327_L3 "RC0603FR-07825KL" 0603 209.203,96.059 r180 top value=825k (schematic designator R327)
R327_N "RC0603FR-07825KL" 0603 97.441,10.203 r270 top value=825k (schematic designator R327)
R328_L1 "RC0603FR-0771K5L" 0603 44.044,138.108 r90 top value=71.5k (schematic designator R328)
R328_L2 "RC0603FR-0771K5L" 0603 128.044,123.108 r90 top value=71.5k (schematic designator R328)
R328_L3 "RC0603FR-0771K5L" 0603 212.044,95.108 r90 top value=71.5k (schematic designator R328)
R328_N "RC0603FR-0771K5L" 0603 98.392,13.044 r180 top value=71.5k (schematic designator R328)
R329 "CRCW0402200RJNED" 0402L 206.35,7.681 r0 top value=200
R330 "CRCW040210K0FKED" 0402L 206.304,6.626 r0 top value=10.0k
R331 "MCS0402MD1002BE100" 0402L 265.621,60.68 r0 top value=10.0k
R332 "CRCW040210R0JNED" 0402L 265.2,58.8 r90 top value=10
R333 "MCS0402MD1002BE100" 0402L 266.2,55.2 r0 top value=10.0k
R334 "RCS06030000Z0EA" 0603 187.3,47.6 r180 top value=0
RN1 "RES60A410QDWVRQ1" DWV0008A-MFG 136.635,270.95 r270 bottom
RN2 "RES60A410QDWVRQ1" DWV0008A-MFG 120.905,270.95 r270 bottom
RN3 "RES60A410QDWVRQ1" DWV0008A-MFG 107.095,270.95 r270 bottom
TP1 "5001" Keystone5001 137.4,89.8 r90 top
TP2 "5011" Keystone5011 253,279 r0 top
TP3 "5011" Keystone5011 228,279 r0 top
TP4 "5011" Keystone5011 212,279 r0 top
TP5 "5010" Keystone5010 181.729,3.275 r180 top
TP6 "5011" Keystone5011 165.5,2 r180 top
TP7 "5011" Keystone5011 267,280 r0 top
TP8 "5011" Keystone5011 193,129 r0 top
TP9 "5011" Keystone5011 110,144 r0 top
TP10 "5011" Keystone5011 27,4 r0 top
TP11 "5011" Keystone5011 274.2,68.2 r0 top
TP12 "5011" Keystone5011 129.8,232.6 r0 top
TP13 "5011" Keystone5011 54.9,103.8 r0 top
U1 "ISOTMP35BEDFQRQ1" DFQ0007A-MFG 190.9,85.3 r90 top
U2 "TMCS1126B5QDVGR" DVG0010A-MFG 89,243 r0 top
U3 "OPA4388IPWR" PW0014A-MFG 272.8,47.25 r0 top
U4 "TMCS1126B5QDVGR" DVG0010A-MFG 106.209,221 r90 top
U5 "TMCS1126B5QDVGR" DVG0010A-MFG 192,197.165 r90 top
U6 "TMCS1126B5QDVGR" DVG0010A-MFG 32.5,103.706 r45 top
U7 "AMC0330RDWVR" DWV0008A-MFG 133.005,255.6 r270 top
U8 "AMC0330RDWVR" DWV0008A-MFG 119.135,255.55 r270 top
U9 "AMC0330RDWVR" DWV0008A-MFG 107.77,255.6 r270 top
U10 "UCC33421DHAR" DHA0016A-MFG 98.725,255.925 r90 top
U11 "AMC0381D" DFX0015A-MFG 83.854,97.929 r90 top
U12 "OPA2392DR" D0008A-MFG 260.6,58.775 r0 top
U13 "UCC33421DHAR" DHA0016A-MFG 95.438,97.929 r270 top
U14 "OPA4388IDR" D0014A-MFG 176.586,68.684 r270 top
U15 "SN74LVC126APWR" PW0014A_N 229.871,60.452 r0 top
U16 "SN74LVC126APWR" PW0014A_N 214.448,60.175 r0 top
U17 "SN74LVC126APWR" PW0014A_N 213.916,27.402 r180 top
U18 "SN74LVC126APWR" PW0014A_N 229.6,29.1 r180 top
U19 "TPS259474LRPWT" RPW0010A-MFG 175.979,10.925 r180 top
U20 "TVS1401DRBR" DRB0008A 180.729,14.85 r90 top
U21 "TPSM863252RDXR" RDX0007A-MFG 165.633,25.904 r180 top
U22 "TLV75533PDRVR" DRV0006A 149.05,16.826 r0 top
U23 "ISOW1044DFM" DFM0020A-MFG 287.695,26.9 r270 top
U24 "TSM24CADBZR" DBZ0003A-MFG 271.25,21.25 r90 top
U25 "TSM24CADBZR" DBZ0003A-MFG 265.25,21.25 r90 top
U27_L1 "LMG3660R015KLF" KLF0016A-MFG 81.75,172.75 r180 bottom (schematic designator U27)
U27_L2 "LMG3660R015KLF" KLF0016A-MFG 165.75,157.75 r180 bottom (schematic designator U27)
U27_L3 "LMG3660R015KLF" KLF0016A-MFG 249.75,129.75 r180 bottom (schematic designator U27)
U27_N "LMG3660R015KLF" KLF0016A-MFG 63.75,50.75 r270 bottom (schematic designator U27)
U28_L1 "ISO7721FDWV" DWV0008A 91.25,125 r90 top (schematic designator U28)
U28_L2 "ISO7721FDWV" DWV0008A 175.25,110 r90 top (schematic designator U28)
U28_L3 "ISO7721FDWV" DWV0008A 259.25,82 r90 top (schematic designator U28)
U28_N "ISO7721FDWV" DWV0008A 111.5,60.25 r180 top (schematic designator U28)
U29_L1 "UCC33421-Q1" DWX0016A-MFG 97.65,124.855 r90 top (schematic designator U29)
U29_L2 "UCC33421-Q1" DWX0016A-MFG 181.697,109.85 r90 top (schematic designator U29)
U29_L3 "UCC33421-Q1" DWX0016A-MFG 265.7,81.9 r90 top (schematic designator U29)
U29_N "UCC33421-Q1" DWX0016A-MFG 111.75,66.772 r180 top (schematic designator U29)
U30_L1 "TLV61046ADBVR" DBV0006A_N 96.913,136.345 r180 top (schematic designator U30)
U30_L2 "TLV61046ADBVR" DBV0006A_N 180.913,121.345 r180 top (schematic designator U30)
U30_L3 "TLV61046ADBVR" DBV0006A_N 264.913,93.345 r180 top (schematic designator U30)
U30_N "TLV61046ADBVR" DBV0006A_N 100.155,65.913 r270 top (schematic designator U30)
U31_L1 "LMG3660R015KLF" KLF0016A-MFG 76.75,153.5 r180 bottom (schematic designator U31)
U31_L2 "LMG3660R015KLF" KLF0016A-MFG 160.75,138.5 r180 bottom (schematic designator U31)
U31_L3 "LMG3660R015KLF" KLF0016A-MFG 244.75,110.5 r180 bottom (schematic designator U31)
U31_N "LMG3660R015KLF" KLF0016A-MFG 83,45.75 r270 bottom (schematic designator U31)
U32_L1 "ISO7721FDWV" DWV0008A 74.91,125.5 r90 top (schematic designator U32)
U32_L2 "ISO7721FDWV" DWV0008A 158.91,110.5 r90 top (schematic designator U32)
U32_L3 "ISO7721FDWV" DWV0008A 242.91,82.5 r90 top (schematic designator U32)
U32_N "ISO7721FDWV" DWV0008A 111,43.91 r180 top (schematic designator U32)
U33_L1 "SN74LVC1G11DRYR" DRY0006A 69.956,115.267 r270 top (schematic designator U33)
U33_L2 "SN74LVC1G11DRYR" DRY0006A 153.956,100.267 r270 top (schematic designator U33)
U33_L3 "SN74LVC1G11DRYR" DRY0006A 237.956,72.267 r270 top (schematic designator U33)
U33_N "SN74LVC1G11DRYR" DRY0006A 121.233,38.956 r0 top (schematic designator U33)
U34_L1 "UCC33421-Q1" DWX0016A-MFG 81.5,125 r90 top (schematic designator U34)
U34_L2 "UCC33421-Q1" DWX0016A-MFG 165.5,110 r90 top (schematic designator U34)
U34_L3 "UCC33421-Q1" DWX0016A-MFG 249.5,82 r90 top (schematic designator U34)
U34_N "UCC33421-Q1" DWX0016A-MFG 111.5,50.5 r180 top (schematic designator U34)
U35_L1 "TLV61046ADBVR" DBV0006A_N 80.275,136.116 r180 top (schematic designator U35)
U35_L2 "TLV61046ADBVR" DBV0006A_N 164.275,121.116 r180 top (schematic designator U35)
U35_L3 "TLV61046ADBVR" DBV0006A_N 248.275,93.116 r180 top (schematic designator U35)
U35_N "TLV61046ADBVR" DBV0006A_N 100.384,49.275 r270 top (schematic designator U35)
U36_L1 "LMG3660R015KLF" KLF0016A-MFG 58.75,153.5 r180 bottom (schematic designator U36)
U36_L2 "LMG3660R015KLF" KLF0016A-MFG 142.75,138.5 r180 bottom (schematic designator U36)
U36_L3 "LMG3660R015KLF" KLF0016A-MFG 226.75,110.5 r180 bottom (schematic designator U36)
U36_N "LMG3660R015KLF" KLF0016A-MFG 83,27.75 r270 bottom (schematic designator U36)
U37_L1 "ISO7721FDWV" DWV0008A 51.129,125.5 r90 top (schematic designator U37)
U37_L2 "ISO7721FDWV" DWV0008A 135.129,110.5 r90 top (schematic designator U37)
U37_L3 "ISO7721FDWV" DWV0008A 219.129,82.5 r90 top (schematic designator U37)
U37_N "ISO7721FDWV" DWV0008A 111,20.129 r180 top (schematic designator U37)
U38_L1 "LP5951MG-2.5/NOPB" DCK0005A_N 48.078,145.675 r0 bottom (schematic designator U38)
U38_L2 "LP5951MG-2.5/NOPB" DCK0005A_N 132.078,130.675 r0 bottom (schematic designator U38)
U38_L3 "LP5951MG-2.5/NOPB" DCK0005A_N 216.078,102.675 r0 bottom (schematic designator U38)
U38_N "LP5951MG-2.5/NOPB" DCK0005A_N 90.825,17.078 r90 bottom (schematic designator U38)
U39_L1 "UCC33421-Q1" DWX0016A-MFG 57.885,125.208 r90 top (schematic designator U39)
U39_L2 "UCC33421-Q1" DWX0016A-MFG 141.885,110.208 r90 top (schematic designator U39)
U39_L3 "UCC33421-Q1" DWX0016A-MFG 225.885,82.208 r90 top (schematic designator U39)
U39_N "UCC33421-Q1" DWX0016A-MFG 111.292,26.885 r180 top (schematic designator U39)
U40_L1 "TLV61046ADBVR" DBV0006A_N 57.458,136.283 r180 top (schematic designator U40)
U40_L2 "TLV61046ADBVR" DBV0006A_N 141.458,121.283 r180 top (schematic designator U40)
U40_L3 "TLV61046ADBVR" DBV0006A_N 225.458,93.283 r180 top (schematic designator U40)
U40_N "TLV61046ADBVR" DBV0006A_N 100.217,26.458 r270 top (schematic designator U40)
U41_L1 "AMC0311DDWV" DWV0008A-MFG 64.669,125.658 r270 top (schematic designator U41)
U41_L2 "AMC0311DDWV" DWV0008A-MFG 148.669,110.658 r270 top (schematic designator U41)
U41_L3 "AMC0311DDWV" DWV0008A-MFG 232.669,82.658 r270 top (schematic designator U41)
U41_N "AMC0311DDWV" DWV0008A-MFG 110.842,33.669 r0 top (schematic designator U41)
U42_L1 "LMG3660R015KLF" KLF0016A-MFG 53.25,172.75 r180 bottom (schematic designator U42)
U42_L2 "LMG3660R015KLF" KLF0016A-MFG 137.25,157.75 r180 bottom (schematic designator U42)
U42_L3 "LMG3660R015KLF" KLF0016A-MFG 221.25,129.75 r180 bottom (schematic designator U42)
U42_N "LMG3660R015KLF" KLF0016A-MFG 63.75,22.25 r270 bottom (schematic designator U42)
U43_L1 "ISO7721FDWV" DWV0008A 35.978,125.676 r90 top (schematic designator U43)
U43_L2 "ISO7721FDWV" DWV0008A 119.978,110.676 r90 top (schematic designator U43)
U43_L3 "ISO7721FDWV" DWV0008A 203.978,82.676 r90 top (schematic designator U43)
U43_N "ISO7721FDWV" DWV0008A 110.824,4.978 r180 top (schematic designator U43)
U44_L1 "UCC33421-Q1" DWX0016A-MFG 42.429,125.338 r90 top (schematic designator U44)
U44_L2 "UCC33421-Q1" DWX0016A-MFG 126.429,110.338 r90 top (schematic designator U44)
U44_L3 "UCC33421-Q1" DWX0016A-MFG 210.429,82.338 r90 top (schematic designator U44)
U44_N "UCC33421-Q1" DWX0016A-MFG 111.162,11.429 r180 top (schematic designator U44)
U45_L1 "TLV61046ADBVR" DBV0006A_N 41.176,136.384 r180 top (schematic designator U45)
U45_L2 "TLV61046ADBVR" DBV0006A_N 125.176,121.384 r180 top (schematic designator U45)
U45_L3 "TLV61046ADBVR" DBV0006A_N 209.176,93.384 r180 top (schematic designator U45)
U45_N "TLV61046ADBVR" DBV0006A_N 100.116,10.176 r270 top (schematic designator U45)
ZZ1 "This Assembly Note is for PCB labels only" AssemblyNoteLabel 333.37,4.996 r90 top
ZZ2 "These assemblies are ESD sensitive, ESD precautions shall be observed." AssemblyNote 296.6,44.8 r90 top
ZZ3 "These assemblies must be clean and free from flux and all contaminants. Use of no clean flux is not acceptable." AssemblyNote 296.7,43.8 r90 top
ZZ4 "These assemblies must comply with workmanship standards IPC-A-610 Class 2, unless otherwise specified." AssemblyNote 322.12,36.496 r90 top

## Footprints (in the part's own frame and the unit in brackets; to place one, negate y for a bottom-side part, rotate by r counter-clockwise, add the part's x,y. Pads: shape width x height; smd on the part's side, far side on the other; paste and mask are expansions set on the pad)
0402 [mm] "0402 from SM-752 data"
  rect 0.8x0.6 smd: 1(-0.6,0) 2(0.6,0)
  silkscreen extent -1.22,-0.52 1.22,0.52, body extent -0.55,-0.3 0.55,0.3, height 0.6
0402L [mm] "0402 from SM-752 data"
  rect 0.6x0.5 smd: 1(-0.5,0) 2(0.5,0)
  body extent -0.55,-0.3 0.55,0.3, height 0.6
0402S [mil] "Based on C0402S footprint from PADS legacy"
  rect 15x24 smd: 1(-20,0) 2(20,0)
  body extent -22,-12 22,12, height 24
0603 [mm] "0603 from SM-752 data"
  rect 1x0.95 smd: 1(-0.8,0) 2(0.8,0)
  silkscreen extent -1.52,-0.69 1.52,0.69, body extent -0.87,-0.47 0.87,0.47, height 1
0805_HV [mil] "0805 with 30mil clearance between pads"
  rect 50x63 smd: 1(-40,0) 2(40,0)
  silkscreen extent -74,-40 74,40, body extent -43,-29 43,29, height 57
1206 [mm] "1206 from SM-752 data"
  rect 1.3x1.85 smd: 1(-1.45,0) 2(1.45,0)
  silkscreen extent -2.4,-1.21 2.4,1.21, body extent -1.7,-0.9 1.7,0.9, height 1.35
1206_180 [mm] "1206_180"
  rect 1.1x1.6 smd: 1(-1.7,0) 2(1.7,0)
  silkscreen extent -0.9,-1 0.9,1, body extent -1.75,-0.95 1.75,0.95, height 1.8
1206_180L [mm] "1206_180"
  rect 1.1x1.75 smd: 1(-1.35,0) 2(1.35,0)
  silkscreen extent -0.4,-0.77 0.4,0.77, body extent -1.75,-0.95 1.75,0.95, height 1.8
1210_270 [mm] "1210"
  rect 1.3x2.7 smd: 1(-1.45,0) 2(1.45,0)
  silkscreen extent -2.32,-1.57 2.32,1.57, body extent -1.7,-1.35 1.7,1.35, height 2.7
1812_254 [mm] "SMD, 2-Leads, Body 4.8x3.4mm"
  rect 1.6x3.4 smd: 1(-2,0) 2(2,0)
  silkscreen extent -0.8,-1.7 0.8,1.7, body extent -2.4,-1.7 2.4,1.7, height 2.54
2225 [mm] "Chip Capacitor, Body 5.7x6.4mm, IPC Medium Density"
  rect 1.6x6.8 smd: 1(-2.6,0) 2(2.6,0)
  silkscreen extent -3.72,-3.69 3.72,3.69, body extent -2.95,-3.4 2.95,3.4, height 2
AssemblyNote [mm] "Assembly Note"
AssemblyNoteLabel [mm] "Assembly Note for PCB Labels"
CE_Mark_5mm [mm] "Minimum text height for CE Mark"
  silkscreen extent -3.5,-2.5 3.5,2.5
Cliff_FCR7350B [mm] "Panel Socket, R/A, TH"
  rrect50% 2.7x2.7 hole 2.2: 1(0,0)
  round 1.7 hole 1.2: 2(-5.08,3.8) 3(5.08,3.8) 4(5.08,-6.36) 5(-5.08,-6.36)
  silkscreen extent -6.01,-13.5 6.01,5.5, body extent -6,-27.5 6,5.5, height 12.3
Cliff_FCR7350R [mm] "Panel Socket, R/A, TH"
  rrect50% 2.7x2.7 hole 2.2: 1(0,0)
  round 1.7 hole 1.2: 2(-5.08,3.8) 3(5.08,3.8) 4(5.08,-6.36) 5(-5.08,-6.36)
  silkscreen extent -6.01,-13.5 6.01,5.5, body extent -6,-27.5 6,5.5, height 12.3
controlCARD-120HSEC [mm] "Pads are not numbered according to Samtec datasheet."
  rect 0.5x2.724 smd: 1(-23.357,-1.678) 2(-23.357,1.722) 3(-22.557,-1.678) 4(-22.557,1.722) 5(-21.757,-1.678) 6(-21.757,1.722) 7(-20.957,-1.678) 8(-20.957,1.722) 9(-20.157,-1.678) 10(-20.157,1.722) 11(-19.357,-1.678) 12(-19.357,1.722) 13(-18.557,-1.678) 14(-18.557,1.722) 15(-17.757,-1.678) 16(-17.757,1.722) 17(-16.957,-1.678) 18(-16.957,1.722) 19(-16.157,-1.678) 20(-16.157,1.722) 21(-15.357,-1.678) 22(-15.357,1.722) 23(-14.557,-1.678) 24(-14.557,1.722) 25(-13.757,-1.678) 26(-13.757,1.722) 27(-12.957,-1.678) 28(-12.957,1.722) 29(-12.157,-1.678) 30(-12.157,1.722) 31(-11.357,-1.678) 32(-11.357,1.722) 33(-10.557,-1.678) 34(-10.557,1.722) 35(-9.757,-1.678) 36(-9.757,1.722) 37(-8.957,-1.678) 38(-8.957,1.722) 39(-8.157,-1.678) 40(-8.157,1.722) 41(-7.357,-1.678) 42(-7.357,1.722) 43(-6.557,-1.678) 44(-6.557,1.722) 45(-5.757,-1.678) 46(-5.757,1.722) 47(-4.957,-1.678) 48(-4.957,1.722) 49(-4.157,-1.678) 50(-4.157,1.722) 51(-3.357,-1.678) 52(-3.357,1.722) 53(-2.557,-1.678) 54(-2.557,1.722) 55(-1.757,-1.678) 56(-1.757,1.722) 57(2.243,-1.678) 58(2.243,1.722) 59(3.043,-1.678) 60(3.043,1.722) 61(3.843,-1.678) 62(3.843,1.722) 63(4.643,-1.678) 64(4.643,1.722) 65(5.443,-1.678) 66(5.443,1.722) 67(6.243,-1.678) 68(6.243,1.722) 69(7.043,-1.678) 70(7.043,1.722) 71(7.843,-1.678) 72(7.843,1.722) 73(8.643,-1.678) 74(8.643,1.722) 75(9.443,-1.678) 76(9.443,1.722) 77(10.243,-1.678) 78(10.243,1.722) 79(11.043,-1.678) 80(11.043,1.722) 81(11.843,-1.678) 82(11.843,1.722) 83(12.643,-1.678) 84(12.643,1.722) 85(13.443,-1.678) 86(13.443,1.722) 87(14.243,-1.678) 88(14.243,1.722) 89(15.043,-1.678) 90(15.043,1.722) 91(15.843,-1.678) 92(15.843,1.722) 93(16.643,-1.678) 94(16.643,1.722) 95(17.443,-1.678) 96(17.443,1.722) 97(18.243,-1.678) 98(18.243,1.722) 99(19.043,-1.678) 100(19.043,1.722) 101(19.843,-1.678) 102(19.843,1.722) 103(20.643,-1.678) 104(20.643,1.722) 105(21.443,-1.678) 106(21.443,1.722) 107(22.243,-1.678) 108(22.243,1.722) 109(23.043,-1.678) 110(23.043,1.722) 111(23.843,-1.678) 112(23.843,1.722) 113(24.643,-1.678) 114(24.643,1.722) 115(25.443,-1.678) 116(25.443,1.722) 117(26.243,-1.678) 118(26.243,1.722) 119(27.043,-1.678) 120(27.043,1.722)
  round 0.025 hole 1.27 unplated mask+0.876: 181(-24.857,0.022) 182(28.543,1.522)
  round 1.348 hole 0.84: 185(-27.207,0.022) 186(30.893,0.022)
  silkscreen extent -32.11,-3.86 35.8,3.9, body extent -31.75,-3.48 35.3,3.52, height 12.35
CUI_PJ-002AH-SMT [mm] "CUI"
  rect 2.8x2.4 smd: 1(-3.05,5.7) 1A(3.05,5.7) 2(-3.05,-5.7) 3(3.05,-5.7)
  round 1 hole 1.6 unplated: MH1(-3.05,0)
  round 1.524 hole 1.8 unplated: MH2(1.45,0)
  silkscreen extent -8.05,-4.5 6.75,5.45, body extent -8.05,-6.3 6.75,6.3, height 11.2
D0008A-MFG [mm]
  rrect17% 1.55x0.6 smd paste+0 mask+0: 1(-2.7,1.905) 2(-2.7,0.635) 3(-2.7,-0.635) 4(-2.7,-1.905) 5(2.7,-1.905) 6(2.7,-0.635) 7(2.7,0.635) 8(2.7,1.905)
  silkscreen extent -4.17,-2.5 1.5,2.5, body extent -3.57,-2.75 3.57,2.75, height 0.25
D0014A-MFG [mm]
  rrect17% 1.55x0.6 smd paste-1000 mask+0: 1(-2.7,3.81) 2(-2.7,2.54) 3(-2.7,1.27) 4(-2.7,0) 5(-2.7,-1.27) 6(-2.7,-2.54) 7(-2.7,-3.81) 8(2.7,-3.81) 9(2.7,-2.54) 10(2.7,-1.27) 11(2.7,0) 12(2.7,1.27) 13(2.7,2.54) 14(2.7,3.81)
  silkscreen extent -4.15,-4.38 1.55,4.38, body extent -3.57,-4.62 3.57,4.62, height 0.25
DBV0006A_N [mm] "SOT23, 6-Leads, Body 2.9x1.6mm, Pitch 0.95mm, Lead Span 2.8mm, IPC Medium Density"
  rrect17% 1x0.6 smd: 1(-1.375,0.95) 2(-1.375,0) 3(-1.375,-0.95) 4(1.375,-0.95) 5(1.375,0) 6(1.375,0.95)
  silkscreen extent -1.68,-1.55 0.5,1.55, body extent -1.42,-1.46 1.42,1.46, height 1.12
DBZ0003A-MFG [mm]
  rrect17% 1.3x0.6 smd paste+0 mask+0: 1(-1.05,0.95) 2(-1.05,-0.95) 3(1.05,0)
  silkscreen extent -0.7,-1.52 0.7,1.52, body extent -1.8,-1.62 1.8,1.62, height 0.25
DCK0005A_N [mm] "SOT353, 5-Leads, Body 2x1.3mm, Pitch 0.65mm, Lead Span 2.1mm, IPC Medium Density"
  rrect25% 0.85x0.4 smd: 1(-1.125,0.65) 2(-1.125,0) 3(-1.125,-0.65) 4(1.125,-0.65) 5(1.125,0.65)
  silkscreen extent -1.48,-1.02 0.55,1.1, body extent -1.14,-1 1.14,1, height 0.95
DFM0020A-MFG [mm]
  rrect17% 2.1x0.6 smd paste+0 mask+0: 1(-4.85,5.715) 2(-4.85,4.445) 3(-4.85,3.175) 4(-4.85,1.905) 5(-4.85,0.635) 6(-4.85,-0.635) 7(-4.85,-1.905) 8(-4.85,-3.175) 9(-4.85,-4.445) 10(-4.85,-5.715) 11(4.85,-5.715) 12(4.85,-4.445) 13(4.85,-3.175) 14(4.85,-1.905) 15(4.85,-0.635) 16(4.85,0.635) 17(4.85,1.905) 18(4.85,3.175) 19(4.85,4.445) 20(4.85,5.715)
  silkscreen extent -6.57,-6.47 3.4,6.47, body extent -6,-6.72 6,6.72, height 0.25
DFQ0007A-MFG [mm]
  rrect17% 1.55x0.6 smd paste+0 mask+0: 1(-2.7,1.905) 2(-2.7,0.635) 3(-2.7,-0.635) 4(-2.7,-1.905) 5(2.7,-1.905) 7(2.7,1.905)
  rrect6% 1.55x2.36 smd paste+0 mask+0: 6(2.7,0)
  silkscreen extent -4.14,-2.5 1.55,2.5, body extent -3.57,-2.75 3.57,2.75, height 0.25
DFX0015A-MFG [mm]
  rrect22% 1.85x0.45 smd paste+0 mask+0: 1(-4.975,5.525) 2(-4.975,-2.925) 3(-4.975,-3.575) 4(-4.975,-4.225) 5(-4.975,-4.875) 6(-4.975,-5.525) 7(4.975,-5.525) 8(4.975,-4.875) 9(4.975,0.325) 10(4.975,0.975) 11(4.975,1.625) 12(4.975,2.275) 13(4.975,2.925) 14(4.975,3.575) 15(4.975,5.525)
  silkscreen extent -6.57,-6.47 3.5,6.47, body extent -6,-6.72 6,6.72, height 0.25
